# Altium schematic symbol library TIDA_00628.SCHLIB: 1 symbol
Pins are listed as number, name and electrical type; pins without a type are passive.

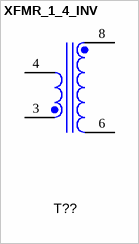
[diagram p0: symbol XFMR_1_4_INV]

## XFMR_1_4_INV
designator T??, comment Used in BOM report  (value not drawn)
1 Input 4 Output XFMR; CompType: Transformer; U/M: EA
pins: 3, 4, 6, 8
